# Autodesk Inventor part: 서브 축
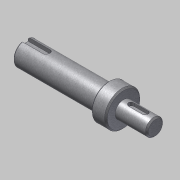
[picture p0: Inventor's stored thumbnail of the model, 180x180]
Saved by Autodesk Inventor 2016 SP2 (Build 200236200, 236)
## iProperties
Created: 2016-04
Part Number: 서브 축
Document SubType Name: Modeling
Designer: mdu
Density: 1 g/cm^3
Mass: 19.9624 g
Surface Area: 57.7178 cm^2
Volume: 19.9624 cm^3
Material: 강철, 연강
Appearance: 금속-강(스테인리스, 브러시됨)
Author: mdu
Revision Number: 1
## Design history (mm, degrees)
sketch "스케치1"
  geometry: L1 (-16.331, 0)-(-108.831, 0); L2 (-16.331, 0)-(-16.331, -6); L3 (-16.331, -6)-(-38.831, -6); L4 (-38.831, -12.5)-(-46.5, -12.5); L5 (-46.5, -8.5)-(-108.831, -8.5); L6 (-108.831, -8.5)-(-108.831, 0); L7 (-46.5, -8.5)-(-46.5, -12.5); L8 (-38.831, -6)-(-38.831, -12.5); L9 (-46.5, 12.249)-(-46.5, -12.249) reference; L10 (-38.831, -17)-(-38.831, 17) reference; 2 further points
  constraints: 17 end point, 4 perpendicular, 2 collinear, 2 parallel, 1 horizontal, 1 midpoint, 1 point on line
  dimensions: "d1" = 12 diameter of L3 L1; "d2" = 25 diameter of L4 L1; "d3" = 17 diameter of L5 L1; "d18" = 22.5 distance of L2.end L3.end; "d20" = 70 distance between parallel lines of L6 L8; "d21" = 7.66872 distance of L4.start L4.end (derived)
revolve "회전1" sketch "스케치1" stored, may be unused: angle "d5" = 90 deg
chamfer "모따기1" distance "d6" = 1; stored, may be unused: second distance "d7" = 2, angle "d8" = 45 deg
node "작업 평면1"
sketch "스케치2"
  geometry: L1 (11.25, 5)-(11.25, -5) reference; L2 (-5.75, -2)-(4.25, -2); L3 (4.25, 2)-(-5.75, 2); A1 r 2 centre (4.25, 0) between (4.25, -2) and (4.25, 2); A2 r 2 centre (-5.75, 0) between (-5.75, 2) and (-5.75, -2); 2 further points
  constraints: 4 end point, 4 point on circle, 4 tangent, 2 centre point, 1 horizontal alignment, 1 midpoint, 1 parallel, 1 perpendicular
  dimensions: "d9" = 4 distance between parallel lines of L2 L3; "d10" = 14 dimension on A1 A2; "d11" = 5 distance edge to line of A1 L1
extrude "돌출1" cut sketch "스케치2" distance "d12" = 2.5; taper "d13" = 0 deg
node "작업 평면2"
sketch "스케치3"
  geometry: L1 (-31.166, -7.5)-(-31.166, 7.5) reference; L2 (-31.166, 2.5)-(-15.666, 2.5); L3 (-15.666, -2.5)-(-31.166, -2.5); A1 r 2.5 centre (-15.666, 0) between (-15.666, -2.5) and (-15.666, 2.5); 2 further points
  constraints: 4 end point, 2 perpendicular, 2 point on circle, 2 point on line, 2 tangent, 1 centre point, 1 horizontal alignment, 1 midpoint
  dimensions: "d14" = 5 distance between parallel lines of L3 L2; "d15" = 18 dimension on A1 L1
extrude "돌출2" cut sketch "스케치3" distance "d16" = 3; taper "d17" = 0 deg
sketch "스케치4"
  geometry: C1 r 12.5 at (0, 0) reference; 1 further point
extrude "돌출3" join sketch "스케치4" distance "d22" = 3; taper "d23" = 0 deg
chamfer "모따기2" distance "d24" = 1; stored, may be unused: second distance "d25" = 2, angle "d26" = 45 deg
node "솔리드1"
node "참조4"
node "참조5"
